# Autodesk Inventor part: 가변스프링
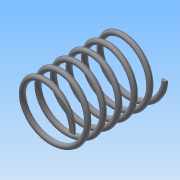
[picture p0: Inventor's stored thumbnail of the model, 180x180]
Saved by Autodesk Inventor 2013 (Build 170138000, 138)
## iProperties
Created: 2018-06
Part Number: 가변스프링
Material: 일반
Document SubType Name: Modeling
Designer: Administrator
Density: 1 g/cm^3
Author: Administrator
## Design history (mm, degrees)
sketch "스케치1"
  geometry: L1 (0, 0)-(0, 73.25); L2 (0, 0)-(22.5, 0); L3 (0, 73.25)-(22.5, 73.25); C1 r 2 at (22.5, 0)
  constraints: 6 end point, 1 centre point, 1 coincident, 1 parallel, 1 perpendicular, 1 vertical
  dimensions: "d0" = 73.25 distance of L1.start L1.end (derived); "d1" = 22.5 distance of L1.start L2.end; "d2" = 22.5 distance of L1.end L3.end; "d3" = 4 diameter of C1
feature "코일1" sketch "스케치1" pitch "d4" = 10; turns "d6" = 6; dims "d5" = 73.25 (= d0), "d7" = 0, angle "d8" = 90 deg, angle "d9" = 90 deg, "d10" = 0, "d11" = 0
sketch "스케치2"
  geometry: L1 (73.25, 27.5)-(0, 27.5); L2 (0, 27.5)-(0, -27.5); L3 (0, -27.5)-(73.25, -27.5); L4 (73.25, -27.5)-(73.25, 27.5); 2 further points
  constraints: 8 end point, 2 parallel, 1 coincident, 1 horizontal, 1 midpoint, 1 perpendicular
  dimensions: "d12" = 73.25 distance of L1.start L1.end (derived); "d14" = 55 distance of L3.end L1.start
extrude "돌출1" sketch "스케치2" stored distance "d15" = 10; taper "d16" = 0 deg
node "솔리드1"
